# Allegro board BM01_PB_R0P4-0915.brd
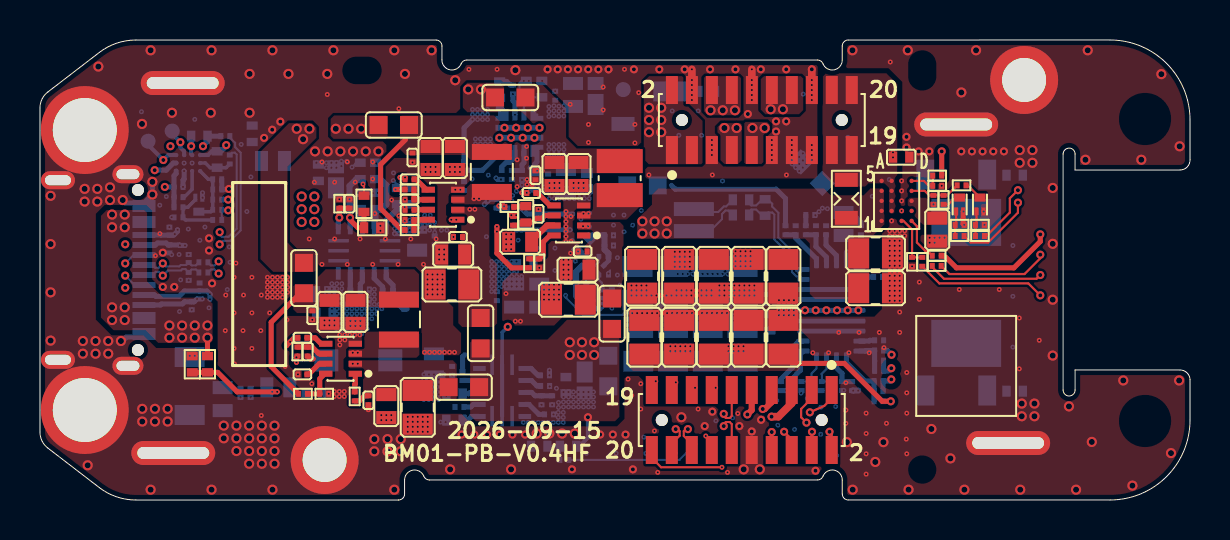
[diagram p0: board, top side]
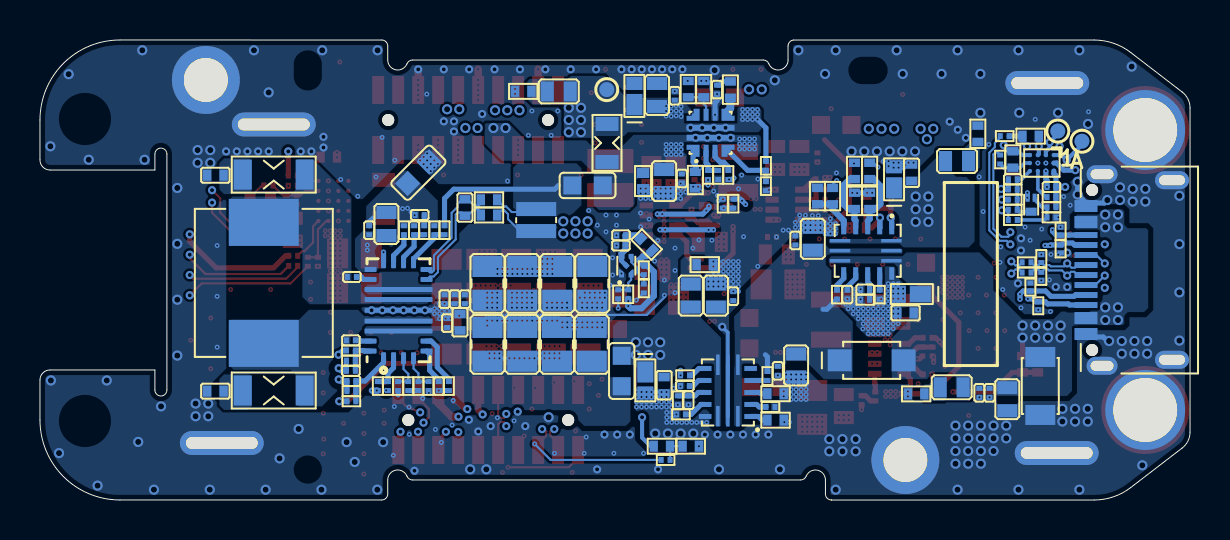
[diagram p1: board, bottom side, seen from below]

Outline 57.54 x 23 mm; copper layers: TOP, GND2, SIG3, SIG4, GND5, BOTTOM. Coordinates in mm from the lower left corner of the outline.
Outline path: 0,19.61 arc(0.1,20.05) 0.39,20.4 2.97,22.38 arc(3.83,22.84) 4.8,23 19.83,23 arc(20.03,22.91) 20.11,22.7 20.11,22 arc(20.52,21.51) 21.08,21.81 arc(21.19,21.95) 21.35,22 38.9,22 arc(39.07,21.95) 39.18,21.81 arc(39.74,21.51) 40.14,22 40.14,22.7 arc(40.23,22.91) 40.44,23 53.54,23 arc(56.37,21.83) 57.54,19 57.54,17.02 arc(57.4,16.65) 57.04,16.5 51.79,16.5 51.79,17.3 arc(51.49,17.6) 51.19,17.3 51.19,5.5 arc(51.49,5.2) 51.79,5.5 51.79,6.5 57.04,6.5 arc(57.39,6.36) 57.54,6.02 57.54,4 arc(56.37,1.17) 53.54,0 40.44,0 arc(40.23,0.09) 40.14,0.3 40.14,1 arc(39.74,1.49) 39.18,1.19 arc(39.07,1.05) 38.9,1 19.48,1 arc(19.32,1.05) 19.21,1.19 arc(18.65,1.49) 18.24,1 18.24,0.3 arc(18.15,0.09) 17.94,0 4.8,0 arc(3.83,0.16) 2.97,0.62 0.39,2.6 arc(0.1,2.95) 0,3.39 0,19.61

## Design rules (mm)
constraint set DEFAULT: min track width 0.107, pair gap 0.127
net group 90_BILLBOARD_D_X1: nets 90_BILLBOARD_DN_X1 90_BILLBOARD_DP_X1
net group 90_BILLBOARD_D_X2: nets 90_BILLBOARD_DN_X2 90_BILLBOARD_DP_X2
net group DP1: nets DSP_SBU1_X3 DSP_SBU2_X3
net group PW_5V_SENSE_: nets PW_5V_SENSE_N PW_5V_SENSE_P
net group 20V: nets MT7231_MOUT PD_USP_VBUS_X1 PW_5V_VIN VCC5-20V_SYS_X1 VCC5-20V_SYS_X2 VCC5-20V_SYS_X3
net group DP2: nets N17338604
nets with their own width: min track width 0.109; nets CHARGE_OC CHARGE_PE1 CHG_VBUS_MON GPIO2_CHG_VBUS_DISCHARGE GPIO4_CHG_VBUS_CTRL GPIO5_PLUG_VBUS_DISCHARGE GPIO6_PLUG_VBUS_CTRL

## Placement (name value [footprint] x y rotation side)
C501  2.2nF/50V  [C0402]  48.77 5.44 0 bottom
C502  2.2nF/50V  [C0402]  48.77 16.24 0 bottom
C503  22uF/25V  [C0805]  35.15 7.78 90 bottom
C504  22uF/25V  [C0805]  33.41 7.78 90 bottom
C505  100nF/25V  [C0201]  41.99 7.99 180 bottom
C506  100nF/25V  [C0201]  41.93 11.15 180 bottom
C507  1uF/25V  [C0402]  36.53 8.89 90 bottom
C508  100nF/25V  [C0201]  37.17 8.85 90 bottom
C509  4.7uF/25V  [C0603]  40.21 13.8 270 bottom
C510  100nF/25V  [C0201]  41.07 13.49 270 bottom
C511  100nF/25V  [C0201]  41.99 6.46 180 bottom
C512  100nF/25V  [C0201]  41.96 5.95 0 bottom
C513  47uF/10V  [C0805]  35.15 10.83 270 bottom
C514  47uF/10V  [C0805]  33.41 10.83 270 bottom
C515  47uF/10V  [C0805]  31.66 10.83 270 bottom
C516  100nF/25V  [C0201]  36.79 10.04 270 bottom
C517  100nF/25V  [C0201]  37.3 10.04 270 bottom
C518  100nF/25V  [C0201]  36.28 10.04 270 bottom
C519  10nF/25V  [C0201]  37.59 5.7 90 bottom
C520  220nF/25V  [C0402]  36.28 14.63 90 bottom
C521  100pF/50V  [C0201]  38.82 13.49 90 bottom
C522  10nF/25V  [C0201]  38.54 14.25 0 bottom
C523  100nF/10V  [C0201]  28.47 12.73 0 bottom
C524  10nF/25V  [C0201]  28.47 13.23 0 bottom
C525  47uF/10V  [C0805]  29.9 10.83 270 bottom
C526  22uF/25V  [C0805]  30.24 8.14 90 top
C527  22uF/25V  [C0805]  31.98 8.14 90 top
C528  22uF/25V  [C0805]  33.72 8.14 90 top
C529  22uF/25V  [C0805]  29.93 7.78 90 bottom
C530  22uF/25V  [C0805]  35.46 8.14 90 top
C531  22uF/25V  [C0805]  31.67 7.78 90 bottom
C532  22uF/25V  [C0805]  37.2 8.14 90 top
C533  47uF/10V  [C0805]  33.72 11.19 270 top
C534  47uF/10V  [C0805]  30.13 11.19 270 top
C535  47uF/10V  [C0805]  31.98 11.19 270 top
C536  47uF/10V  [C0805]  35.46 11.19 270 top
C537  47uF/10V  [C0805]  37.2 11.19 270 top
C601  4.7uF/35V  [C0603]  18.87 13.06 90 bottom
C602  4.7uF/35V  [C0603]  11.92 5.64 0 bottom
C603  100nF/35V  [C0201]  19.75 12.98 90 bottom
C604  4.7uF/35V  [C0603]  11.66 16.95 180 bottom
C605  1uF/35V  [C0402]  14.24 9.36 0 bottom
C606  1uF/35V  [C0402]  13.93 16.37 90 bottom
C607  100nF/25V  [C0201]  16.26 10.52 0 bottom
C608  100nF/25V  [C0201]  15.49 14.82 90 top
C609  10nF/25V  [C0201]  17.14 10.27 270 bottom
C610  4.7uF/35V  [C0603]  19.71 6.73 270 bottom
C611  100nF/35V  [C0201]  20.62 6.46 270 bottom
C612  4.7uF/35V  [C0603]  24.98 10.22 90 bottom
C613  1uF/35V  [C0402]  26.31 5.74 270 bottom
C614  100nF/35V  [C0201]  22.86 10.2 90 bottom
C615  4.7uF/35V  [C0603]  23.72 10.22 90 bottom
C616  100nF/25V  [C0201]  25.09 4.99 270 bottom
C617  10nF/25V  [C0201]  25.28 5.7 0 bottom
C701  22uF/25V  [C0805]  26.44 10.02 180 top
C702  10uF/25V  [C0603]  26.9 11.51 180 top
C703  100nF/25V  [C0201]  27.15 12.43 180 top
C704  100nF/25V  [C0201]  24.59 15.35 180 top
C705  22uF/10V  [C0603]  25.74 16.3 270 top
C706  22uF/10V  [C0603]  26.95 16.3 270 top
C707  100nF/10V  [C0201]  24.79 16.24 270 top
C708  68nF/50V  [C0603]  24.03 12.91 180 top
C709  100nF/25V  [C0201]  24.94 14.31 90 top
C710  22uF/25V  [C0805]  18.9 4.63 270 top
C711  10uF/25V  [C0603]  17.33 4.7 270 top
C712  100nF/25V  [C0201]  16.43 4.99 270 top
C713  100nF/25V  [C0201]  13.13 8.11 180 top
C714  22uF/10V  [C0603]  14.49 9.41 270 top
C715  22uF/10V  [C0603]  15.78 9.41 270 top
C716  100nF/25V  [C0201]  13.39 7.42 270 top
C717  100nF/10V  [C0201]  13.63 9.24 270 top
C718  10nF/25V  [C0201]  13.13 6.28 180 top
C719  22uF/25V  [C0805]  20.61 10.78 180 top
C720  10uF/25V  [C0603]  20.67 12.28 180 top
C721  100nF/25V  [C0201]  20.92 13.15 180 top
C722  100nF/25V  [C0201]  18.49 16.04 180 top
C723  22uF/10V  [C0603]  19.54 17.1 270 top
C724  22uF/10V  [C0603]  20.76 17.1 270 top
C725  100nF/10V  [C0201]  18.64 17.13 270 top
C726  100nF/25V  [C0201]  18.49 15.02 180 top
C727  10nF/25V  [C0201]  18.49 14.51 180 top
C801  100nF/35V  [C0201]  10.03 5.36 270 bottom
C802  4.7uF/35V  [C0603]  9.14 5.04 270 bottom
C803  100nF/35V  [C0201]  10.54 5.36 270 bottom
C804  1uF/10V  [C0201]  6.93 15.65 0 bottom
C805  100nF/10V  [C0201]  8.87 16.04 0 bottom
C901  22uF/10V  [C0603]  26.31 15.95 270 bottom
C902  100nF/25V  [C0201]  25.42 16.08 270 bottom
C903  100nF/25V  [C0201]  25.78 20.22 90 bottom
C904  4.7uF/35V  [C0603]  31.58 20.43 0 bottom
C905  22uF/10V  [C0603]  26.67 20.25 90 bottom
C907  3.3nF/25V  [C0201]  23.67 20.52 270 bottom
C1101  22uF/25V  [C0805]  41.81 12.33 0 top
C1102  22uF/25V  [C0805]  41.81 10.59 0 top
C1103  4.7uF/35V  [C0603]  44.89 13.52 270 top
C1104  1uF/25V  [C0402]  43.09 17.14 0 top
D601  LMBR4020H3T5G  [DFN_2P_1D05_1D6X0D8_H0D42-CA]  13.92 10.3 0 bottom
D602  LMBR4020H3T5G  [DFN_2P_1D05_1D6X0D8_H0D42-CA]  14.81 16.04 90 bottom
D603  LMBR4020H3T5G  [DFN_2P_1D05_1D6X0D8_H0D42-CA]  27.25 5.98 270 bottom
D606  LMBR340FT1G  [SOD123_2P_3D2_3D65X1D75_H1D15_CA]  15.93 6.98 180 bottom
D901  LMBR4020H3T5G  [DFN_2P_1D05_1D6X0D8_H0D42-CA]  27.8 20.2 90 bottom
H1  Mechanical HOLE  [PAD-C4D4D3D2]  2.24 18.5 0 top
H2  Mechanical HOLE  [PAD-C4D4D3D2]  2.24 4.5 0 top
H3  Mechanical HOLE  [PAD-C4D2D2]  14.24 2 0 top
H4  Mechanical HOLE  [PAD-C4D2D2]  49.24 21 0 top
H5  Mechanical HOLE  [PAD-O4D6X1D6D3D6X0D6]  7.14 20.85 0 top
H6  Mechanical HOLE  [PAD-O4D6X1D6D3D6X0D6]  6.67 2.35 0 top
H7  Mechanical HOLE  [PAD-O4D6X1D6D3D6X0D6]  45.84 18.78 0 top
H8  Mechanical HOLE  [PAD-O4D6X1D6D3D6X0D6]  48.44 2.85 0 top
J801  UCA11-1600B2ANL-H03  [TYPEC_16-4P_0D5_10D24X7D35_H4D7]  3.23 11.5 90 bottom
J1001  1mm_pitch_10x2 Male Connector  [FH_2X10P_1_10D2X3D8_H2D55]  36.12 19 0 top
J1002  1mm_pitch_10x2 Male Connector  [FH_2X10P_1_10D2X3D8_H2D55]  35.11 4 180 top
L501  4.7uH/8A  [L_2P_6D05_7D3X6D8_H3]  46.34 10.86 90 bottom
L701  4.7uH/1.3A  [L_2P_1D7_2D5X2_H1D2]  29.01 16.1 90 top
L702  1.5uH/2.5A  [L_2P_2_2D5X2_H1D2]  17.96 9.02 90 top
L703  1.5uH/2.5A  [L_2P_2_2D5X2_H1D2]  22.61 16.4 90 top
Q801  L2N7002KN3T5G  [SOT883_3P_0D35_0D6X1_H0D53]  7.95 14.77 0 bottom
Q1101  L2N7002KN3T5G  [SOT883_3P_0D35_0D6X1_H0D53]  46.02 14.78 0 top
Q1102  L2N7002KN3T5G  [SOT883_3P_0D35_0D6X1_H0D53]  47.03 14.78 0 top
R501  2.2R_1%  [R1206]  45.85 5.48 180 bottom
R502  2.2R_1%  [R1206]  45.85 16.27 180 bottom
R503  0R  [R0201]  40.64 5.7 270 bottom
R504  0R  [R0201]  41.99 7.48 0 bottom
R506  0R  [R0201]  40.13 5.7 90 bottom
R507  0R  [R0201]  41.99 6.97 180 bottom
R508  147K_1%  [R0201]  41.96 4.94 180 bottom
R509  115K_1%  [R0201]  41.96 5.44 180 bottom
R510  10mOHM  [R0508_1P25X2]  32.72 14 90 bottom
R511  100K_1%  [R0201]  37.3 13.49 90 bottom
R512  10R_1%  [R0402]  35.08 14.25 180 bottom
R513  10R_1%  [R0402]  35.08 15.01 180 bottom
R514  49.9K_1%  [R0201]  37.08 5.7 270 bottom
R515  30.1K_1%  [R0201]  37.81 13.49 270 bottom
R516  150K_1%  [R0201]  39.33 13.49 270 bottom
R517  10K_1%  [R0201]  38.32 13.49 270 bottom
R518  0R_1%  [R0402]  27.19 12.77 45 bottom
R520  0R  [R0201]  39.62 5.7 270 bottom
R521  0R  [R0201]  38.1 5.7 270 bottom
R522  0R  [R0201]  27.33 10.58 90 bottom
R523  0R  [R0201]  28.61 10.28 90 bottom
R524  10K  [R0201]  39.12 5.7 90 bottom
R525  10K  [R0201]  38.61 5.7 90 bottom
R526  10K  [R0201]  27.33 11.49 270 bottom
R527  10K  [R0201]  28.11 10.28 90 bottom
R601  3.6R_1%  [R0402]  10.62 18.31 270 bottom
R602  3.6R_1%  [R0402]  13.7 5.31 180 bottom
R603  0R_1%  [R0402]  16.03 16.45 90 bottom
R604  0R_1%  [R0402]  17.88 15.2 90 bottom
R605  0R_1%  [R0402]  16.21 14.81 270 top
R606  0R_1%  [R0402]  16.79 16.45 270 bottom
R607  10K  [R0201]  17.66 10.27 90 bottom
R608  100K_1%  [R0402]  18.64 15.2 270 bottom
R609  100K_1%  [R0402]  16.03 14.96 270 bottom
R610  100K_1%  [R0402]  16.62 13.61 180 top
R611  100K_1%  [R0402]  16.79 14.96 270 bottom
R612  8.2K_1%  [R0201]  16.26 10.02 180 bottom
R613  8.2K_1%  [R0201]  14.98 14.82 270 top
R614  200K_1%  [R0201]  15.53 10.27 90 bottom
R615  10K  [R0201]  21.14 6.2 90 bottom
R616  4.7K  [R0402]  20.74 5.31 0 bottom
R617  4.7K  [R0402]  20.74 3.99 0 bottom
R618  3.6R_1%  [R0402]  24.28 11.77 0 bottom
R619  10K  [R0201]  25.27 6.23 180 bottom
R620  10K  [R0201]  20.99 4.65 0 bottom
R621  8.2K_1%  [R0201]  25.63 4.99 90 bottom
R622  200K_1%  [R0201]  25.47 4.28 180 bottom
R623  330K_1%  [R0402]  26.42 2.69 0 bottom
R624  47K_1%  [R0402]  24.98 2.69 0 bottom
R625  0R  [R0201]  26.24 2 180 bottom
R701  300K_1%  [R0201]  23.67 13.97 270 top
R703  3.16K_1%  [R0201]  24.48 11.83 270 top
R704  0R  [R0201]  23.48 14.66 180 top
R705  1K_1%  [R0201]  24.99 11.83 90 top
R706  300K_1%  [R0201]  12.88 7.42 90 top
R707  10K_1%  [R0201]  13.16 5.31 180 top
R708  20K_1%  [R0201]  14.23 5.31 180 top
R709  100K  [R0201]  15.75 5.18 90 top
R710  300K_1%  [R0201]  18.49 15.53 0 top
R711  2.49K_1%  [R0201]  18.49 13.5 180 top
R712  20K_1%  [R0201]  18.49 14 0 top
R713  42.2K_1%  [R0201]  23.38 14.82 270 bottom
R714  100K_1%  [R0201]  22.85 14.82 270 bottom
R715  22K_1%  [R0402]  24.31 14.28 270 top
R801  100K  [R0201]  6.93 15.15 180 bottom
R802  10K  [R0201]  8.87 15.02 180 bottom
R803  10K  [R0201]  6.93 14.64 0 bottom
R804  10K  [R0201]  8.87 15.53 0 bottom
R805  0R  [R0201]  8.87 14 0 bottom
R806  10K  [R0201]  6.93 14.13 180 bottom
R807  0R_1%  [R0402]  7.97 18.19 0 bottom
R808  0R_1%  [R0402]  8.86 17.03 270 bottom
R809  0R  [R0201]  8.87 14.51 0 bottom
R810  0R  [R0201]  8.18 11.88 180 bottom
R811  0R  [R0201]  8.18 11.37 180 bottom
R812  0R  [R0201]  9.27 18.19 180 bottom
R813  0R  [R0201]  9.5 17.03 270 bottom
R901  0R  [R0805]  29.17 17.85 90 bottom
R902  100K  [R0402]  24.75 16 90 bottom
R903  0R  [R0402]  23 20.52 270 bottom
R904  47K_1%  [R0201]  24.12 16.25 270 bottom
R905  33K_1%  [R0201]  21.22 16.71 90 bottom
R906  3.6R_1%  [R0402]  33.36 20.43 180 bottom
R907  1.1K_1%  [R0402]  24.33 20.55 270 bottom
R908  10K_1%  [R0201]  23.1 16.25 90 bottom
R909  12K_1%  [R0201]  21.22 15.69 90 bottom
R910  10K_1%  [R0201]  23.61 16.25 90 bottom
R911  0R  [R0402]  25.11 20.55 90 bottom
R1001  330K_1%  [R0402]  8.38 6.79 90 top
R1002  47K_1%  [R0402]  7.62 6.79 270 top
R1101  0R  [R0805]  40.35 15.06 90 top
R1102  30K_1%  [R0201]  44.7 15.01 90 top
R1103  84.5K_1%  [R0201]  45.21 15.01 90 top
R1104  30K_1%  [R0201]  46.11 15.73 180 top
R1105  0R  [R0201]  46.02 13.2 0 top
R1106  0R  [R0201]  47.03 13.2 0 top
R1107  10K_1%  [R0201]  46.02 13.76 180 top
R1108  10K_1%  [R0201]  47.03 13.76 180 top
R1109  0R  [R0201]  44.87 11.71 180 top
R1110  0R  [R0201]  44.14 11.91 90 top
R1111  10K_1%  [R0201]  43.64 11.91 90 top
R1112  10K_1%  [R0201]  44.87 12.22 180 top
R1113  160K_1%  [R0201]  44.89 16.22 0 top
R1114  10K_1%  [R0201]  44.89 15.71 180 top
SL501  -  [SL0603]  28.43 6.45 270 bottom
SL502  -  [SL0603]  30.14 15.73 180 bottom
SL503  -  [SL0603]  38.61 16.37 135 bottom
SL701  -  [SL0603]  23.53 20.12 180 top
SL702  -  [SL0603]  28.63 9.32 90 top
SL703  -  [SL0603]  21.21 5.64 180 top
SL704  -  [SL0603]  13.21 11.1 90 top
SL705  -  [SL0603]  22.05 8.34 90 top
SL706  -  [SL0603]  17.7 18.75 180 top
TP801  X_Testpoint_SMDC20  [TPC30]  5.41 17.94 0 bottom
TP802  X_Testpoint_SMDC20  [TPC30]  6.62 18.45 0 bottom
TP901  TP  [TPC30]  29.18 20.52 180 bottom
TVS801  SMF20CA  [SOD123_2P_2D9_3D75X1D75_H1D2]  7.49 5.7 90 bottom
TVS802  AR0521P0LV  [DFN_2P_0D4_0D6X0D3_H0D34]  6.48 13.44 270 bottom
TVS803  AR0521P0LV  [DFN_2P_0D4_0D6X0D3_H0D34]  6.48 12.56 90 bottom
TVS804  AR0521P0LV  [DFN_2P_0D4_0D6X0D3_H0D34]  7.59 9.71 90 bottom
TVS805  AR0521P0LV  [DFN_2P_0D4_0D6X0D3_H0D34]  7.44 11.18 90 bottom
TVS806  AR0521P0LV  [DFN_2P_0D4_0D6X0D3_H0D34]  7.44 12.07 270 bottom
TVS807  AR0521P0LV  [DFN_2P_0D4_0D6X0D3_H0D34]  7.99 10.65 270 bottom
TVS901  JEB07DF  [DFN_2P_0D8_1X0D6_H0D55]  27.37 15.95 270 bottom
U501  TPS55289RYQR  [VQFN_21P_0D5_5X3_H1]  39.6 9.49 90 bottom
U502  TMP110DIDPWR  [X2SON_5P_0D48_0D8X0D8_H0D4]  28.21 11.72 180 bottom
U601  MT7232NQJR  [QFN_16P_0D5_2D5X3D2_H0D8]  16.13 12.46 270 bottom
U602  MT7231NQJR  [QFN_16P_0D5_2D5X3D2_H0D8]  23.12 5.38 0 bottom
U701  LA3522BS  [SOT583_8P_0D5_2D1X1D6_H0D6]  26.47 13.98 90 top
U702  LA3522BS  [SOT583_8P_0D5_2D1X1D6_H0D6]  15.04 7.06 90 top
U703  LA3522BS  [SOT583_8P_0D5_2D1X1D6_H0D6]  20.17 14.77 90 top
U801  NX20P0407UKAZ  [WLCSP_12P_0D4_1D27X1D67_H0D57]  7.41 16.85 270 bottom
U901  LM73100RPWR  [VQFN-HR-10P_0D475_2X2_H1]  23.99 18.36 90 bottom
U1101  KTS1865CEIAA-TA  [WLCSP_20P_0D5_2D71X2D16_H0D6]  42.86 14.96 90 top

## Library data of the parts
C501-C537 C601-C617 C701-C727 C801-C805 C901-C905 C907 C1101-C1104 = Cap_np
D601-D603 D606 D901 = SBD-A
H1-H8 = Mechanical HOLE
J801 = UCB11-1600B1ANL-H06
J1001 J1002 = HEADER 20X2_5
L501 L701-L703 = Coil
Q801 Q1101 Q1102 = NMOS-L2N7002KN3T5G
R501-R504 R506-R509 R511-R518 R520-R527 R601-R625 R701 R703-R715 R801-R813 R901-R911 R1001 R1002 R1101-R1114 = Resistor
R510 = TRL050810FR010P05Z
SL501-SL503 SL701-SL706 = SL0603
TP801 TP802 = J PCB_TP_SMDC20
TP901 = TP
TVS801-TVS807 TVS901 = TVS-BiA
U501 = BUCK&BOOST-PTPS55289RYQR
U502 = TMP110DIDPWR
U601 = Power Switch-MT7232NQJR
U602 = Power Switch-MT7231NQJR
U701-U703 = LA3522BS
U801 = NX20P0407UKAZ
U901 = LM73100RPWR
U1101 = KTS1865CEIAA-TA

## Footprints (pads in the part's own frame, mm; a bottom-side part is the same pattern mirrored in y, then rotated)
C0201
  rect 0.25x0.3 smd: 1(-0.225,0) 2(0.225,0)
C0402
  rect 0.42x0.55 smd: 1(-0.41,0) 2(0.41,0)
C0603
  rect 0.65x1 smd: 1(-0.575,0) 2(0.575,0)
C0805
  rect 1.05x1.5 smd: 1(-0.845,0) 2(0.845,0)
DFN_2P_0D4_0D6X0D3_H0D34
  rect 0.25x0.3 smd: 1(-0.2,0) 2(0.2,0)
DFN_2P_0D8_1X0D6_H0D55
  rect 0.5x0.6 smd: 1(-0.4,0) 2(0.4,0)
DFN_2P_1D05_1D6X0D8_H0D42-CA
  rect 1.05x0.8 smd: 1(-0.425,0)
  rect 0.65x0.8 smd: 2(0.625,0)
FH_2X10P_1_10D2X3D8_H2D55
  round 0.6 hole 0.6 unplated: (-4,0) (4,0)
  rect 0.6x1.4 smd: 1(-4.5,-1.5) 2(-4.5,1.5) 3(-3.5,-1.5) 4(-3.5,1.5) 5(-2.5,-1.5) 6(-2.5,1.5) 7(-1.5,-1.5) 8(-1.5,1.5) 9(-0.5,-1.5) 10(-0.5,1.5) 11(0.5,-1.5) 12(0.5,1.5) 13(1.5,-1.5) 14(1.5,1.5) 15(2.5,-1.5) 16(2.5,1.5) 17(3.5,-1.5) 18(3.5,1.5) 19(4.5,-1.5) 20(4.5,1.5)
L_2P_1D7_2D5X2_H1D2
  rect 1.2x2.3 smd: 1(-0.85,0) 2(0.85,0)
L_2P_2_2D5X2_H1D2
  rect 0.8x2 smd: 1(-1,0) 2(1,0)
L_2P_6D05_7D3X6D8_H3
  rect 2.35x3.5 smd: 1(-3.025,0) 2(3.025,0)
PAD-C4D2D2
  round 3.4 hole 2.2: 1(0,0)
PAD-C4D4D3D2
  round 4.4 hole 3.2: 1(0,0)
PAD-O4D6X1D6D3D6X0D6
  oval 4.2x1.2 hole 3.6x0.6: 1(0,0)
QFN_16P_0D5_2D5X3D2_H0D8
  rect 0.627x0.25 smd: 1(-1.136,1.2) 2(-1.136,0.6) 3(-1.136,0) 4(-1.136,-0.6) 5(-1.136,-1.2) 9(1.136,-1.2) 10(1.136,-0.6) 11(1.136,0) 12(1.136,0.6) 13(1.136,1.2)
  rect 0.175x1.027 smd: 6(-0.5,-1.387) 7(0,-1.387) 8(0.5,-1.387) 14(0.5,1.186) 15(0,1.186) 16(-0.5,1.186)
R0201
  rect 0.25x0.3 smd: 1(-0.225,0) 2(0.225,0)
R0402
  rect 0.42x0.55 smd: 1(-0.41,0) 2(0.41,0)
R0508_1P25X2
  rect 0.7x2 smd: 1(-0.55,0) 2(0.55,0)
R0805
  rect 0.7x1.15 smd: 1(-0.95,0) 2(0.95,0)
R1206
  rect 0.9x1.5 smd: 1(-1.55,0) 2(1.55,0)
SL0603
  rect 0.9x0.9 smd: 1(-0.762,0) 2(0.762,0)
SOD123_2P_2D9_3D75X1D75_H1D2
  rect 1x1.5 smd: 1(-1.45,0) 2(1.45,0)
SOD123_2P_3D2_3D65X1D75_H1D15_CA
  rect 1.2x1.1 smd: 1(-1.6,0) 2(1.6,0)
SOT583_8P_0D5_2D1X1D6_H0D6
  rect 0.3x0.67 smd: 1(-0.75,-0.74) 2(-0.25,-0.74) 3(0.25,-0.74) 4(0.75,-0.74) 5(0.75,0.74) 6(0.25,0.74) 7(-0.25,0.74) 8(-0.75,0.74)
SOT883_3P_0D35_0D6X1_H0D53
  rect 0.2x0.4 smd: 1(-0.175,-0.35) 2(0.175,-0.35)
  rect 0.55x0.4 smd: 3(0,0.35)
TPC30
  round 0.75 smd: 1(0,0)
TYPEC_16-4P_0D5_10D24X7D35_H4D7
  round 0.6 hole 0.6 unplated: (-4,1.668) (4,1.668)
  rect 0.3x1.15 smd: A1(-3.35,1.973) A4(-2.55,1.973) A5(-1.25,1.973) A6(-0.25,1.973) A7(0.25,1.973) A8(1.25,1.973) A9(2.55,1.973) A12(3.35,1.973) B1(3.05,1.973) B4(2.25,1.973) B5(1.75,1.973) B6(0.75,1.973) B7(-0.75,1.973) B8(-1.75,1.973) B9(-2.25,1.973) B12(-3.05,1.973)
  oval 0.9x1.55 hole 0.5x1.15: G1(-4.79,1.167) G2(4.79,1.167)
  oval 0.9x1.7 hole 0.5x1.3: G3(-4.49,-2.332) G4(4.49,-2.332)
VQFN-HR-10P_0D475_2X2_H1
  custom 0.15x0.15 smd: 1(-0.9,0.875) 4(-0.9,-0.875) 7(0.9,-0.875) 10(0.9,0.875)
  rect 0.6x0.25 smd: 2(-0.9,0.225) 3(-0.9,-0.225) 8(0.9,-0.225) 9(0.9,0.225)
  rect 0.3x2.4 smd: 5(-0.25,0) 6(0.25,0)
VQFN_21P_0D5_5X3_H1
  rrect 0.6x0.25 smd: 1(-2.4,0.75) 2(-2.4,0.25) 3(-2.4,-0.25) 4(-2.4,-0.75) 14(2.4,-0.75) 15(2.4,-0.25) 16(2.4,0.25) 17(2.4,0.75)
  rrect 0.25x0.6 smd: 5(-2.04,-1.4) 6(-1.54,-1.4) 12(1.54,-1.4) 13(2.04,-1.4) 18(2.04,1.4) 19(1.54,1.4) 20(-1.54,1.4) 21(-2.04,1.4)
  rrect 0.25x3.4 smd: 7(-1.04,0) 8(-0.54,0) 9(0,0) 10(0.54,0) 11(1.04,0)
WLCSP_12P_0D4_1D27X1D67_H0D57
  round 0.22 smd: A1(-0.4,0.6) A2(0,0.6) A3(0.4,0.6) B1(-0.4,0.2) B2(0,0.2) B3(0.4,0.2) C1(-0.4,-0.2) C2(0,-0.2) C3(0.4,-0.2) D1(-0.4,-0.6) D2(0,-0.6) D3(0.4,-0.6)
WLCSP_20P_0D5_2D71X2D16_H0D6
  round 0.22 smd: A1(-1,0.75) A2(-0.5,0.75) A3(0,0.75) A4(0.5,0.75) A5(1,0.75) B1(-1,0.25) B2(-0.5,0.25) B3(0,0.25) B4(0.5,0.25) B5(1,0.25) C1(-1,-0.25) C2(-0.5,-0.25) C3(0,-0.25) C4(0.5,-0.25) C5(1,-0.25) D1(-1,-0.75) D2(-0.5,-0.75) D3(0,-0.75) D4(0.5,-0.75) D5(1,-0.75)
X2SON_5P_0D48_0D8X0D8_H0D4
  custom 0.062x0.062 smd: 1(-0.24,-0.39) 2(0.24,-0.39) 4(0.24,0.39) 5(-0.24,0.39)
  rect 0.25x0.25 smd rot 135: 3(0,0)

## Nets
0V9_BST: C722.1 U703.5
0V9_EN: C726.1 R710.2 U703.6
0V9_FB: R711.1 R712.2 U703.8
0V9_PG: R704.2 R713.2 R714.2 U703.1
0V9_SS: C727.1 U703.7
3V3_BST: C704.1 U701.5
3V3_EN_X1: C709.1 R701.2 R715.2 U701.6
3V3_FB: R703.1 R705.2 U701.8
3V3_SS: C708.1 U701.7
GND: C501.2 C502.2 C503.2 C504.2 C507.2 C508.2 C513.2 C514.2 C515.2 C516.2 C517.2 C518.2 C523.2 C524.2 C525.2 C526.2 C527.2 C528.2 C529.2 C530.2 C531.2 C532.2 C533.2 C534.2 C535.2 C536.2 C537.2 C601.2 C603.2 C605.2 C606.2 C607.2 C608.2 C609.2 C610.2 C611.2 C613.2 C614.2 C615.2 C616.2 C617.2 C701.2 C702.2 C703.2 C705.2 C706.2 C707.2 C708.2 C709.2 C710.2 C711.2 C712.2 C714.2 C715.2 C716.2 C717.2 C718.2 C719.2 C720.2 C721.2 C723.2 C724.2 C725.2 C726.2 C727.2 C801.2 C802.2 C803.2 C804.2 C805.2 C901.2 C902.2 C903.2 C905.2 C907.2 C1101.2 C1102.2 C1103.2 C1104.2 D601.2 D602.2 D603.2 D901.2 H1.1(HOLE) H2.1(HOLE) H3.1(HOLE) H4.1(HOLE) H5.1(HOLE) H6.1(HOLE) H7.1(HOLE) H8.1(HOLE) J801.A1 J801.A12 J801.B1 J801.B12 J801.G1 J801.G2 J801.G3 J801.G4 J1001.4 J1001.5 J1001.10 J1001.11 J1001.13 J1001.15 J1001.16 J1002.10 Q801.2(SOURCE) Q1101.2(SOURCE) Q1102.2(SOURCE) R601.1 R602.1 R608.1 R609.1 R610.1 R611.1 R612.1 R613.1 R614.1 R616.1 R617.1 R618.1 R620.1 R621.1 R622.1 R624.1 R705.1 R708.1 R712.1 R713.1 R804.2 R806.2 R902.1 R906.1 R907.1 R909.1 R910.1 R1002.1 R1102.1 R1107.1 R1108.1 R1111.1 R1114.1 SL503.2 TVS801.1 TVS802.1 TVS803.1 TVS804.1 TVS805.1 TVS806.1 TVS807.1 TVS901.2 U501.9 U502.1 U601.13 U602.13 U701.4 U702.4 U703.4 U801.B3 U901.8 U1101.B1 U1101.C3 U1101.C4 U1101.C5
VCC5-20V_SYS: C612.1 C613.1 D603.1(C) R623.2 SL501.1 SL702.1 SL703.1 SL705.1 U602.8 U602.14(VOUT2)
VCC5-20V_SYS_X1: C701.1 C702.1 C703.1 R701.1 SL702.2 U701.2(VIN)
VCC5-20V_SYS_X2: C710.1 C711.1 C712.1 R706.1 R709.1 SL703.2 U702.2(VIN)
VCC5-20V_SYS_X3: C719.1 C720.1 C721.1 R710.1 R714.1 SL705.2 U703.2(VIN)
VCC_0V9: J1001.9 SL706.2
VCC_0V9_X1: C723.1 C724.1 C725.1 L703.2 R711.2 SL706.1
VCC_0V9_X2: C722.2 L703.1 U703.3
VCC_3V3_SYS1: C804.1 J1001.12 J1001.14 R518.1 R524.1 R525.1 R526.1 R527.1 R801.2 R802.1 R803.1 R908.1 R1112.1 SL701.2 U801.A3(VSYS)
VCC_3V3_SYS1_X1: C705.1 C706.1 C707.1 L701.2 R703.2 SL701.1
VCC_3V3_SYS1_X2: C704.2 L701.1 U701.3
VDD12: J1001.6 J1001.8 SL704.2
VDD12_BST: C713.1 U702.5
VDD12_EN: C716.1 R706.2 U702.6
VDD12_FB: R707.1 R708.2 U702.8
VDD12_PG: R709.2 U702.1
VDD12_SS: C718.1 U702.7
VDD12_X1: C714.1 C715.1 C717.1 L702.2 R707.2 SL704.1
VDD12_X2: C713.2 L702.1 U702.3
90_BILLBOARD_DN_X1: J801.A7 J801.B7 R810.2 TVS806.2
90_BILLBOARD_DN_X2: J1002.11 R810.1
90_BILLBOARD_DP_X1: J801.A6 J801.B6 R811.2 TVS805.2
90_BILLBOARD_DP_X2: J1002.12 R811.1
C_PD_ADA_VBUS1: C602.1 C605.1 C801.1 C802.1 C803.1 D601.1(C) D606.2 J801.A4 J801.A9 J801.B4 J801.B9(VBUS_B9) R1001.2 TVS801.2 U601.8 U601.14
CHARGE_OC: J1002.17 R911.2
CHARGE_PE1: J1002.19 R902.2 U901.1
CHG_CC1: J1002.9 U801.A2
CHG_CC2: J1002.7 U801.B2
CHG_VBUS_MON: J1002.5 R1001.1 R1002.2
DSP_AUX_CTR: C805.1 Q801.3 R802.2 R804.1 R809.1 U801.D3
DSP_CC1_X1: J801.A5 TP801.1(TP) TVS807.2 U801.A1
DSP_CC2_X1: J801.B5 TP802.1(TP) TVS802.2 U801.B1
DSP_SBU1_X1: J801.B8 R807.1 TVS804.2 U801.C1
DSP_SBU1_X2: R807.2 R812.2 U801.C2
DSP_SBU1_X3: J1002.16 R812.1
DSP_SBU2_X1: J801.A8 R808.1 TVS803.2 U801.D1
DSP_SBU2_X2: R808.2 R813.2 U801.D2
DSP_SBU2_X3: J1002.18 R813.1
EN2: R1110.2 R1111.2 U1101.C1
GPIO1_ILIMT_2A: J1002.13 R1105.2
GPIO2_CHG_VBUS_DISCHARGE: J1002.3 R603.2
GPIO4_CHG_VBUS_CTRL: J1002.4 R604.2 R805.2 R809.2
GPIO4_CTRL_X1: Q801.1 R803.2 R805.1 R806.1
GPIO5_PLUG_VBUS_DISCHARGE: J1002.1 R605.1 R1109.1
GPIO6_PLUG_VBUS_CTRL: J1002.2 R606.1
GPIO7_KS1865C_EN: J1002.20 R1110.1
GPIO8_ILIMT_3A: J1002.15 R1106.2
HV_AGND1: C509.1 C510.1 C511.1 C512.2 C519.1 C521.2 C522.2 R506.1 R507.1 R509.1 R514.2 R515.1 R516.1 SL503.1 U501.17
I2C0_SCL_X1: J1002.8 R520.2 R523.1
I2C0_SDA_X1: J1002.6 R521.2 R522.1
MOUT: C601.1 C603.1 C610.1 C611.1 D606.1(C) R607.1 R615.2 U601.7 U601.15 U602.6 U602.16
MOUT_ADC: J1002.14 R625.1
MT7231_DISCI: R620.2 U602.2
MT7231_DISCO: R616.2 U602.3
MT7231_EN: R615.1 U602.4
MT7231_FLTB: R619.2 U602.9
MT7231_ILIM: C616.1 R621.2 U602.11
MT7231_MOUT: C614.1 C615.1 R619.1 U602.7 U602.15
MT7231_NOSS: R617.2 U602.1
MT7231_VLIM: R622.2 U602.12
MT7232_DISC1: R605.2 R610.2 U601.2
MT7232_DISC2: R603.1 R609.2 U601.3
MT7232_EN1: R606.2 R611.2 U601.4
MT7232_EN2: R604.1 R608.2 U601.5
MT7232_FLTB: R607.2 U601.9
MT7232_ILIM1: C607.1 R612.2 U601.11
MT7232_ILIM2: C608.1 R613.2 U601.1
MT7232_VLIM: R614.2 U601.12(VLIM)
OVLO: R904.1 R910.2 U901.2
OVLO_17839094: R1113.1 R1114.2 U1101.D5
PD_USP_VBUS: C1104.1 J1001.17 J1001.18 J1001.19 J1001.20 R1101.2 R1113.2 U1101.A5 U1101.B2 U1101.B3 U1101.B4 U1101.B5
PD_USP_VBUS_X1: C604.1 C606.1 C1101.1 C1102.1 D602.1(C) R1101.1 U601.6 U601.16 U1101.A1 U1101.A2 U1101.A3 U1101.A4(VSYS4)
PP5V0: C903.1 C904.1 C905.1 D901.1(C) J1001.1 J1001.2 J1001.3 R901.2 R905.2 TP901.1 U901.6
PP5V0_SYS: C901.1 C902.1 J1001.7 R901.1 R904.2 SL502.2 TVS901.1 U901.5(VIN)
PW_5V_BOOT1: C505.2 U501.20
PW_5V_BOOT2: C506.2 U501.19
PW_5V_BST_SW1: C505.1 L501.1 R501.2 U501.8
PW_5V_BST_SW2: C506.1 L501.2 R502.2 U501.10
PW_5V_CDC: R516.2 U501.16
PW_5V_COMP: C521.1 R517.2 U501.15
PW_5V_DITH: C519.2 U501.5
PW_5V_EN: C512.1 R508.2 R509.2 U501.1
PW_5V_EXTVCC: C511.2 R504.1 R507.2 U501.21
PW_5V_FB: R511.1 R515.2 U501.14
PW_5V_FSW: R514.1 U501.6
PW_5V_MODE: R503.1 R506.2 U501.2
PW_5V_OUT: C513.1 C514.1 C515.1 C516.1 C517.1 C518.1 C525.1 C533.1 C534.1 C535.1 C536.1 C537.1 R510.1 R512.2 U501.11(VOUT)
PW_5V_SENSE_N: C520.2 R513.1 U501.13
PW_5V_SENSE_P: C520.1 R512.1 U501.12
PW_5V_VCC: C509.2 C510.2 R503.2 R504.2 U501.18
PW_5V_VIN: C503.1 C504.1 C507.1 C508.1 C526.1 C527.1 C528.1 C529.1 C530.1 C531.1 C532.1 R508.1 SL501.2 U501.7
SBU_PROT_FLT: R801.1 U801.C3
STS2_ADD: C523.1 C524.1 R518.2 U502.3 U502.5(V+)
TPS55289_I2C0_SCL_X1: R520.1 R524.2 U501.3
TPS55289_I2C0_SDA_X1: R521.1 R525.2 U501.4
TS2_SCL_X1: R523.2 R527.2 U502.2
TS2_SDA_X1: R522.2 R526.2 U502.4
N17338285: C502.1 R502.1
N17338604: R510.2(R) R511.2 R513.2 SL502.1
N17338820: C522.1 R517.1
N17369623: C617.1 U602.10
N17399398: C612.2 R618.2
N17402193: C609.1 U601.10
N17404682: C604.2 R601.2
N17484520: C602.2 R602.2
N17646610: R704.1 R715.1
N17796413: C904.2 R906.2
N17828259: R905.1 R909.2 U901.4
N17829516: R908.2 U901.3
N17829521: R907.2 R911.1 U901.9
N17829622: R903.2 U901.7
N17839181: R1102.2 R1103.2 R1104.2 U1101.D4
N17839235: C1103.1 U1101.D3
N17839251: Q1102.3 R1104.1
N17839328: Q1101.1 R1105.1 R1107.2
N17839336: Q1102.1 R1106.1 R1108.2
N17850318: R1109.2 U1101.C2
N17850490: Q1101.3 R1103.1
N17851575: R623.1 R624.2 R625.2
N17873017: R1112.2 U1101.D1
N17894716: C501.1 R501.1
N178293080: C907.1 R903.1

Pads without a net: U602 5; U701 1; U901 10; U1101 D2

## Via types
v1: diameter 0.25, hole 0.1, TOP to GND2, 592 vias
v2: diameter 0.406, hole 0.203, GND2 to GND5, 451 vias
v3: diameter 0.25, hole 0.1, GND5 to BOTTOM, 687 vias
v4: diameter 0.406, hole 0.203, TOP to BOTTOM, 117 vias
v5: diameter 0.508, hole 0.305, TOP to BOTTOM, 180 vias

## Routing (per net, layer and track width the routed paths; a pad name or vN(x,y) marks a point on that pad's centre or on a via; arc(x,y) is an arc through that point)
0V9_BST: length 0.9
  TOP w0.254: C722.1 18.82,16.04 19.34,15.52 U703.5
0V9_EN: length 1.2
  TOP w0.254: U703.6 19,15.02 19,15.02 C726.1 R710.2
0V9_FB: length 1.2
  TOP w0.254: U703.8 19.04,14.02 19.02,14 R712.2 R711.1
0V9_PG: length 5
  TOP w0.254: R704.2 23.24,14.66 v1(23.22,14.68) 23.19,14.71 v1(22.96,14.71) ; v1(20.83,14.02) v1(20.58,14.02)
  GND2 w0.254: v2(21.16,13.94) 21.08,14.02 v1(20.83,14.02) v1(20.58,14.02) ; v1(23.22,14.68) 23.19,14.71 v1(22.96,14.71) 22.7,14.44 v2(22.7,14.42)
  SIG4 w0.305: v2(22.7,14.42) 22.7,14.2 22.35,13.85 21.24,13.85 v2(21.16,13.94)
  GND5 w0.254: v3(23.33,14.59) v3(23.08,14.59) 22.87,14.59 v2(22.7,14.42)
  BOTTOM w0.254: R714.2 v3(23.08,14.59) v3(23.33,14.59) R713.2
0V9_SS: length 0.7
  TOP w0.254: C727.1 18.97,14.51 18.98,14.52 U703.7
3V3_BST: length 1.2
  TOP w0.254: U701.5 25.52,14.73 24.89,15.35 C704.1
3V3_EN_X1: length 2.3
  TOP w0.254: U701.6 25.27,14.23 25.12,14.08 C709.1 24.84,14.08 24.63,13.87 R715.2 24.05,13.87 23.91,13.74 R701.2
3V3_FB: length 2.1
  TOP w0.254: U701.8 25.51,13.23 25.18,12.9 25.18,12.26 R705.2 R703.1
3V3_SS: length 1.5
  TOP w0.305: C708.1 24.6,12.96 25.37,13.73 U701.7
GND: length 22.4
  TOP w0.254: C712.2 v1(16.43,4.52) ; v1(13.66,7.06) 13.53,7.06 C716.2 ; Q1101.2 46.19,13.81 v1(46.24,13.76)
  TOP w0.381: 38.62,20.78 v1(38.62,21) v4(38.62,21.53) ; v1(32.62,21.53) v1(32.62,21) 32.62,20.78 ; 35.62,20.78 v1(35.62,21) v1(35.62,21.53)
  GND2 w0.254: 44.79,16.47 45.12,16.47 45.12,16.22
  SIG3 w0.109: v2(11.31,7.95) 11.35,7.98 15.42,7.98 15.57,7.83 v2(15.6,7.83)
  GND5 w0.127: 7.44,5.95 7.54,5.95
  BOTTOM w0.102: R907.1 v3(24.21,20.96) 24.09,20.96 23.99,20.85 23.99,20.55
  BOTTOM w0.107: C525.2 29.17,9.25 27.18,9.25 26.3,10.13 v3(26.3,10.23)
  BOTTOM w0.203: v3(8.14,15.37) 8.12,15.35 Q801.2
  BOTTOM w0.254: v5(5.62,15.91) v5(5.62,15.27) 5.21,14.86 J801.A12 ; v3(23.67,20.3) 23.67,19.96 23.76,19.86 v3(23.76,19.26) ; v3(7.16,15.65) 7.16,15.98 7.17,16 7.17,16.01 7.21,16.05 v3(7.21,16.45) ; J801.B12 J801.A1 ; J801.A1 5.21,8.14 ; J801.A1 4.34,8.15 4.14,7.95 v5(4.05,7.95) ; J801.B1 J801.A12 ; J801.A12 4.29,14.85 v5(4.14,15) ; C805.2 R804.2 9.43,15.53 v4(9.45,15.55) ; v3(16.9,15.36) 16.67,15.36 v3(16.65,15.35) 16.64,15.36 v3(16.16,15.36) v3(15.91,15.36) ; v3(18.24,13.32) v3(17.99,13.32) v3(17.74,13.32)
  vias: v1(5.78,12.22) v1(6,13.32) v1(7.5,7.21) v1(7.75,7.21) v1(9.3,10.25) v1(9.27,8.47) v1(9.71,11.14) v1(9.71,9.36) v1(9.71,7.58) v1(9.73,6.81) v1(9.8,11.84) v1(10.18,10.25) v1(10.16,8.47) v1(10.6,11.14) v1(10.6,9.36) v1(10.6,7.58) v1(11.07,10.25) v1(11.05,8.47) v1(11.07,4.22) v1(11.38,11.14) v1(11.38,10.89) v1(11.38,10.64) v1(11.38,10.39) v1(11.38,10.14) v1(11.49,9.36) v1(11.63,11.14) v1(11.63,10.89) v1(11.63,10.64) v1(11.63,10.39) v1(11.63,10.14) v1(11.88,11.14) v1(11.88,10.89) v1(11.88,10.64) v1(11.88,10.39) v1(11.88,10.14) v1(12.13,11.14) v1(12.13,10.89) v1(12.13,10.64) v1(12.13,10.39) v1(12.13,10.14) v1(12.27,6.68) v1(12.38,11.14) v1(12.38,10.89) v1(12.38,10.64) v1(12.38,10.39) v1(12.36,9.01) v1(12.91,6.28) v1(13.47,13.05) v1(13.63,9.01) v1(13.6,5.81) v1(13.73,15.89) v1(14.11,16.91) v1(14.11,11.78) v1(14.24,8.98) v1(14.24,8.73) v1(14.38,20.28) v1(14.49,8.98) v1(14.49,8.73) v1(14.45,5.31) v1(14.74,8.98) v1(14.74,8.73) v1(14.73,5.43) v1(14.73,5.18) v1(14.74,15.89) v1(14.74,13.05) v1(14.98,15.04) v1(15,8.26) v1(15,8.01) v1(15,7.76) v1(14.98,5.43) v1(14.98,5.18) v1(15.23,5.43) v1(15.23,5.18) v1(15.25,8.26) v1(15.25,8.01) v1(15.38,16.91) v1(15.38,11.78) v1(15.49,15.04) v1(15.53,8.96) v1(15.53,8.71) v1(15.5,8.26) v1(15.77,15.89) v1(15.78,8.96) v1(15.78,8.71) v1(15.75,8.26) v1(16.01,13.05) v1(16.03,8.96) v1(16.03,8.71) v1(16,8.26) v1(16.65,16.91) v1(16.65,16.05) v1(16.65,11.78) v1(16.75,14.32) v1(17.03,13.71) v1(17.03,13.46) v1(17.08,4.24) v1(17.08,3.99) v1(17.28,13.05) v1(17.33,4.24) v1(17.33,3.99) v1(17.6,15) v1(17.58,4.24) v1(17.58,3.99) v1(17.92,11.78) v1(17.96,19.57) v1(17.96,14.21) v1(18.27,15.02) v1(18.25,14.66) v1(18.25,13.94) v1(18.4,4.16) v1(18.4,3.91) v1(18.4,3.66) v1(18.4,3.41) v1(18.64,16.88) v1(18.55,13.05) v1(18.65,4.16) v1(18.65,3.91) v1(18.65,3.66) v1(18.65,3.41) v1(18.9,4.16) v1(18.9,3.91) v1(18.9,3.66) v1(18.9,3.41) v1(19.19,11.78) v1(19.24,7.39) v1(19.15,4.16) v1(19.15,3.91) v1(19.15,3.66) v1(19.15,3.41) v1(19.29,16.65) v1(19.29,16.4) v1(19.39,11.28) v1(19.39,11.03) v1(19.39,10.78) v1(19.39,10.53) v1(19.39,10.28) v1(19.4,4.16) v1(19.4,3.91) v1(19.4,3.66) v1(19.4,3.41) v1(19.54,16.65) v1(19.54,16.4) v1(19.49,7.39) v1(19.64,11.28) v1(19.64,11.03) v1(19.64,10.78) v1(19.64,10.53) v1(19.64,10.28) v1(19.74,7.39) v1(19.79,16.65) v1(19.79,16.4) v1(19.82,13.05) v1(19.89,11.28) v1(19.89,11.03) v1(19.89,10.78) v1(19.89,10.53) v1(19.89,10.28) v1(19.97,12.53) v1(19.97,12.28) v1(19.97,12.03) v1(19.99,7.39) v1(20.14,11.28) v1(20.14,11.03) v1(20.14,10.78) v1(20.14,10.53) v1(20.14,10.28) v1(20.22,12.53) v1(20.22,12.28) v1(20.22,12.03) v1(20.24,7.39) v1(20.51,16.65) v1(20.51,16.4) v1(20.49,7.39) v1(20.69,13.15) v1(20.74,7.39) v1(20.76,16.65) v1(20.76,16.4) v1(20.78,15.52) v1(21.01,16.65) v1(21.01,16.4) v1(21.03,15.52) v1(21.46,21.53) v1(22.87,21.53) v1(23.33,13.29) v1(23.33,13.04) v1(23.33,12.79) v1(23.33,12.54) v1(23.32,10.32) v1(23.58,13.29) v1(23.58,13.04) v1(23.58,12.79) v1(23.58,12.54) v1(23.79,8.94) v1(23.88,17.02) v1(23.88,15.67) v1(24.04,8.94) v1(24.35,17.68) v1(24.35,17.09) v1(24.37,16.03) v1(24.37,15.78) v1(24.62,15.78) v1(24.94,14.53) v1(24.99,11.61) v1(25.22,10.77) v1(25.22,10.52) v1(25.22,10.27) v1(25.22,10.02) v1(25.49,15.85) v1(25.49,15.6) v1(25.47,10.77) v1(25.47,10.52) v1(25.47,10.27) v1(25.47,10.02) v1(25.74,15.85) v1(25.74,15.6) v1(25.72,10.77) v1(25.72,10.52) v1(25.72,10.27) v1(25.72,10.02) v1(25.99,15.85) v1(25.99,15.6) v1(25.97,10.77) v1(25.97,10.52) v1(25.97,10.27) v1(25.97,10.02) v1(26.2,12.01) v1(26.2,11.76) v1(26.2,11.51) v1(26.2,11.26) v1(26.2,11.01) v1(26.32,14.43) v1(26.32,14.18) v1(26.32,13.93) v1(26.32,13.68) v1(26.32,13.43) v1(26.32,13.18) v1(26.32,12.93) v1(26.53,19.78) v1(26.45,12.01) v1(26.45,11.76) v1(26.45,11.51) v1(26.45,11.26) v1(26.45,11.01) v1(26.57,14.18) v1(26.57,12.93) v1(26.55,12.34) v1(26.7,15.85) v1(26.7,15.6) v1(26.93,12.43) v1(26.95,15.85) v1(26.95,15.6) v1(27.2,15.85) v1(27.2,15.6) v1(27.44,18.78) v1(27.44,17.88) v1(28.18,20.65) v1(28.18,19.51) v1(29.25,21.53) v1(29.43,6.04) v1(29.6,10.73) v1(29.6,10.48) v1(29.6,10.23) v1(29.63,9.35) v1(29.6,5.23) v1(29.77,18.78) v1(29.77,17.85) v1(29.85,10.73) v1(29.85,10.48) v1(29.85,10.23) v1(29.88,9.35) v1(29.96,20.37) v1(30.1,10.73) v1(30.1,10.48) v1(30.1,10.23) v1(30.13,9.35) v1(30.06,5.81) v1(30.06,4.55) v1(30.35,10.73) v1(30.35,10.48) v1(30.35,10.23) v1(30.38,9.35) v1(30.47,16.25) v1(30.6,10.23) v1(30.63,9.35) v1(30.75,3.45) v1(30.84,10.23) v1(30.88,9.35) v1(30.91,1.38) v1(31.09,10.23) v1(31.13,9.35) v1(31.34,10.23) v1(31.38,9.35) v1(31.59,10.23) v1(31.63,9.35) v1(31.84,10.48) v1(31.84,10.23) v1(31.88,9.35) v1(32.09,10.48) v1(32.09,10.23) v1(32.13,9.35) v1(32.34,10.48) v1(32.34,10.23) v1(32.38,9.35) v1(32.62,20.75) v1(32.62,20.5) v1(32.62,20.25) v1(32.62,20) v1(32.59,10.48) v1(32.59,10.23) v1(32.63,9.35) v1(32.84,10.48) v1(32.84,10.23) v1(32.88,9.35) v1(32.93,4.55) v1(33.09,10.48) v1(33.09,10.23) v1(33.13,9.35) v1(33.34,10.48) v1(33.34,10.23) v1(33.38,9.35) v1(33.62,18) v1(33.62,17.75) v1(33.62,17.5) v1(33.62,17.25) v1(33.64,16.25) v1(33.59,10.48) v1(33.59,10.23) v1(33.63,9.35) v1(33.88,9.35) v1(33.99,10.73) v1(33.99,10.48) v1(33.99,10.23) v1(34.13,9.35) v1(34.24,10.73) v1(34.24,10.48) v1(34.24,10.23) v1(34.38,9.35) v1(34.4,1.38) v1(34.49,10.73) v1(34.49,10.48) v1(34.49,10.23) v1(34.74,10.73) v1(34.74,10.48) v1(34.74,10.23) v1(34.92,4.33) v1(34.99,10.73) v1(34.99,10.48) v1(34.99,10.23) v1(35.24,10.73) v1(35.24,10.48) v1(35.24,10.23) v1(35.49,10.73) v1(35.49,10.48) v1(35.49,10.23) v1(35.62,20.75) v1(35.62,20.5) v1(35.62,20.25) v1(35.62,20) v1(35.74,10.73) v1(35.74,10.48) v1(35.74,10.23) v1(36.62,18) v1(36.62,17.75) v1(36.62,17.5) v1(36.62,17.25) v1(36.62,17) v1(36.98,9.99) v1(36.98,9.74) v1(36.98,9.49) v1(36.98,9.24) v1(37.23,9.99) v1(37.23,9.74) v1(37.23,9.49) v1(37.23,9.24) v1(37.35,16.25) v1(37.48,9.99) v1(37.48,9.74) v1(37.48,9.49) v1(37.48,9.24) v1(37.62,18) v1(37.62,17.75) v1(37.62,17.5) v1(37.62,17.25) v1(37.62,17) v1(37.73,9.99) v1(37.73,9.74) v1(37.73,9.49) v1(37.73,9.24) v1(38.62,20.75) v1(38.62,20.5) v1(38.62,20.25) v1(38.62,20) v1(38.62,17.75) v1(38.62,17.5) v1(38.62,17.25) v1(38.62,17) v1(38.67,7.36) v1(39.46,7.36) v1(39.97,8.38) v1(40.32,5.87) v1(40.32,4.49) v1(40.32,3.83) v1(40.47,7.36) v1(40.98,8.38) v1(41.34,4.34) v1(41.34,3.33) v1(41.34,2.31) v1(41.34,1.29) v1(41.49,7.36) v1(42,8.38) v1(42.23,7.62) v1(42.35,3.83) v1(42.52,13.46) v1(42.52,13.21) v1(42.52,12.96) v1(42.52,12.71) v1(42.52,12.46) v1(42.52,12.21) v1(42.52,11.96) v1(42.52,11.71) v1(42.52,11.46) v1(42.52,11.21) v1(42.52,10.96) v1(42.52,10.71) v1(42.52,10.46) v1(42.52,10.21) v1(42.52,9.96) v1(42.54,21.9) v1(42.61,13.96) v1(42.77,13.46) v1(42.77,13.21) v1(42.77,12.96) v1(42.77,12.71) v1(42.77,12.46) v1(42.77,12.21) v1(42.77,11.96) v1(42.77,11.71) v1(42.77,11.46) v1(42.77,11.21) v1(42.77,10.96) v1(42.77,10.71) v1(42.77,10.46) v1(42.77,10.21) v1(42.77,9.96) v1(43.02,13.46) v1(43.02,13.21) v1(43.02,12.96) v1(43.02,12.71) v1(43.02,12.46) v1(43.02,12.21) v1(43.02,11.96) v1(43.02,11.71) v1(43.02,11.46) v1(43.02,11.21) v1(43.02,10.96) v1(43.02,10.71) v1(43.02,10.46) v1(43.02,10.21) v1(43.02,9.96) v1(43.01,9.4) v1(43.01,8.38) v1(43.11,15.96) v1(43.11,15.46) v1(43.11,14.96) v1(43.27,13.46) v1(43.27,13.21) v1(43.37,6.37) v1(43.37,5.36) v1(43.37,4.34) v1(43.34,3.05) v1(43.37,2.31) v1(43.64,11.69) v1(44,10.89) v1(44,10.04) v1(44.51,13.12) v1(44.51,12.87) v1(44.7,14.78) v1(44.76,13.12) v1(44.76,12.87) v1(45.01,13.12) v1(45.12,15.71) v1(45.26,13.12) v1(46,10.53) v1(46.2,14.43) v1(47.22,14.43) v1(47.26,13.76) v1(48,10.53) v1(49,9.1) v1(49,6.56) v1(50,7.99) v2(4.76,11.61) v2(5.13,13.77) v2(5.28,10.7) v2(5.46,5.85) v2(5.97,13.64) v2(5.98,12.9) v2(6.7,7.35) v2(6.81,11.36) v2(7.45,18.21) v2(7.89,12.6) v2(8.13,11.03) v2(8.08,9.45) v2(8.15,11.72) v2(8.69,17.68) v2(9.11,13.97) v2(9.07,9.51) v2(9.07,6.54) v2(9.42,16.93) v2(9.5,12.23) v2(9.81,18.1) v2(9.78,13.31) v2(10.04,8.79) v2(10.06,6.84) v2(10.15,14.87) v2(10.31,13.98) v2(10.36,12.78) v2(10.55,17.36) v2(10.83,15.55) v2(10.97,4.78) v2(11.31,6.04) v2(11.81,16.44) v2(12.58,6.3) v2(12.62,3.81) v2(12.77,11.8) v2(12.77,11.39) v2(12.77,10.99) v2(12.77,10.58) v2(13.17,11.39) v2(13.17,10.99) v2(13.17,10.58) v2(13.17,10.17) v2(13.28,6.02) v2(13.4,15.9) v2(13.58,10.99) v2(13.58,10.58) v2(13.58,10.17) v2(13.6,6.58) v2(13.99,10.58) v2(13.99,10.17) v2(14.42,15.9) v2(14.44,6.58) v2(14.44,6.02) v2(15.28,6.02) v2(15.86,3.81) v2(16.01,7.83) v2(16.41,7.83) v2(16.49,7.42) v2(16.49,7.02) v2(16.61,15.68) v2(16.82,7.83) v2(16.89,7.42) v2(16.89,7.02) v2(17.23,15.34) v2(17.18,14.94) v2(17.22,7.83) v2(17.3,7.42) v2(17.3,7.02) v2(17.36,1.73) v2(17.52,14.68) v2(17.63,7.83) v2(17.74,17.33) v2(17.74,16.93) v2(17.71,7.42) v2(17.71,7.02) v2(17.9,14.54) v2(17.94,14.94) v2(18.04,7.83) v2(18.11,7.42) v2(18.11,7.02) v2(18.15,17.33) v2(18.16,4.48) v2(18.28,14.29) v2(18.44,7.83) v2(18.52,7.42) v2(18.52,7.02) v2(18.55,17.33) v2(18.6,14.95) v2(18.6,14.55) v2(18.96,17.33) v2(19.01,14.95) v2(19.01,14.55) v2(19.27,7.71) v2(19.33,4.72) v2(19.37,17.33) v2(19.42,15.36) v2(19.42,14.95) v2(19.42,14.55) v2(19.57,3.12) v2(19.68,7.71) v2(19.74,4.7) v2(19.82,15.77) v2(19.82,15.36) v2(19.82,14.95) v2(19.82,14.55) v2(19.77,4.29) v2(20.01,20.86) v2(20.03,14.2) v2(20.03,2.61) v2(20.08,7.71) v2(20.23,15.36) v2(20.23,14.95) v2(20.23,14.55) v2(20.17,13.81) v2(20.2,4.8) v2(20.21,4.36) v2(20.49,7.71) v2(20.45,3.6) v2(20.58,4.94) v2(20.58,4.54) v2(20.58,4.13) v2(20.98,4.94) v2(20.98,4.54) v2(20.98,4.13) v2(21.38,18.26) v2(21.39,4.94) v2(21.39,4.54) v2(21.39,4.13) v2(21.8,4.94) v2(21.8,4.54) v2(21.8,4.13) v2(22.01,9.69) v2(22.19,21.53) v2(22.2,4.94) v2(22.2,4.54) v2(22.2,4.13) v2(22.36,18.57) v2(22.42,9.69) v2(22.49,9.28) v2(22.61,4.94) v2(22.61,4.54) v2(22.61,4.13) v2(22.69,8.93) v2(22.83,9.69) v2(22.89,9.28) v2(23.02,4.54) v2(23.02,4.13) v2(23.23,9.69) v2(23.3,9.28) v2(23.42,4.54) v2(23.42,4.13) v2(23.64,9.69) v2(23.71,9.28) v2(23.83,4.13) v2(24.04,9.69) v2(24.11,9.28) v2(24.45,9.69) v2(24.52,9.28) v2(24.52,8.88) v2(24.52,8.47) v2(24.65,21.53) v2(24.68,13.66) v2(24.86,9.69) v2(24.92,9.28) v2(24.92,8.88) v2(24.92,8.47) v2(24.95,13.97) v2(25.23,13.66) v2(25.26,9.69) v2(25.33,9.28) v2(25.33,8.88) v2(25.33,8.47) v2(25.62,14.22) v2(25.69,13.66) v2(25.67,9.69) v2(25.74,9.28) v2(25.74,8.88) v2(25.74,8.47) v2(25.92,14.53) v2(26,14.04) v2(26.08,9.69) v2(26.14,9.28) v2(26.14,8.88) v2(26.14,8.47) v2(26.31,14.76) v2(26.48,9.69) v2(26.51,4.32) v2(26.51,3.91) v2(26.55,9.28) v2(26.55,8.88) v2(26.55,8.47) v2(26.83,16.44) v2(26.89,9.69) v2(26.92,4.32) v2(26.92,3.91) v2(26.96,9.28) v2(26.96,8.88) v2(26.96,8.47) v2(27.11,19.17) v2(27.11,17.88) v2(27.24,16.44) v2(27.64,16.44) v2(27.71,14.69) v2(27.9,14.33) v2(27.92,4.32) v2(27.92,3.91) v2(27.96,13.93) v2(28.05,16.44) v2(28.12,14.69) v2(28.32,14.33) v2(28.33,4.32) v2(28.33,3.91) v2(28.35,8.23) v2(28.35,7.69) v2(28.35,6.95) v2(28.52,19.22) v2(28.46,16.44) v2(28.53,14.69) v2(28.73,4.32) v2(28.73,3.91) v2(28.86,16.44) v2(29.27,16.44) v2(29.33,8.26) v2(29.33,7.86) v2(29.33,7.45) v2(29.68,16.44) v2(29.73,8.26) v2(29.73,7.86) v2(29.73,7.45) v2(29.91,19.19) v2(29.88,18.41) v2(30.14,8.26) v2(30.14,7.86) v2(30.14,7.45) v2(30.42,21.53) v2(30.42,4.34) v2(30.54,8.26) v2(30.54,7.86) v2(30.54,7.45) v2(30.7,10.96) v2(30.7,10.56) v2(30.95,8.26) v2(30.95,7.86) v2(30.95,7.45) v2(31.1,11.37) v2(31.1,10.96) v2(31.1,10.56) v2(31.34,3.28) v2(31.51,10.96) v2(31.51,10.56) v2(31.46,1.53) v2(31.67,18.41) v2(31.94,10.84) v2(32.09,13.03) v2(32.35,10.84) v2(32.7,4.04) v2(32.75,10.84) v2(33.11,13.03) v2(33.16,10.84) v2(33.32,16.33) v2(33.25,1.53) v2(33.57,10.84) v2(33.67,1.98) v2(34.06,17.85) v2(34.12,13.03) v2(34.51,2.94) v2(35.13,13.03) v2(35.55,2.74) v2(36.14,13.66) v2(36.63,11.6) v2(36.63,11.19) v2(36.63,10.78) v2(36.63,10.38) v2(36.62,9.97) v2(36.61,9.56) v2(36.67,16.15) v2(36.71,8.73) v2(36.96,17.81) v2(36.95,17.24) v2(36.96,16.44) v2(37.04,11.6) v2(37.04,11.19) v2(37.04,10.78) v2(37.04,10.38) v2(37.05,15.03) v2(37.12,8.73) v2(37.12,8.32) v2(37.24,18.1) v2(37.24,17.52) v2(37.25,16.73) v2(37.43,1.98) v2(37.53,18.38) v2(37.45,11.6) v2(37.45,11.19) v2(37.45,10.78) v2(37.45,10.38) v2(37.53,8.73) v2(37.53,8.32) v2(37.53,7.92) v2(37.85,11.6) v2(37.85,11.19) v2(37.85,10.78) v2(37.85,10.38) v2(37.93,8.73) v2(37.93,8.32) v2(37.93,7.92) v2(38.29,20.78) v2(38.28,16.28) v2(38.26,11.6) v2(38.26,11.19) v2(38.26,10.78) v2(38.26,10.38) v2(38.26,9.97) v2(38.34,8.73) v2(38.34,8.32) v2(38.34,7.92) v2(38.58,16.54) v2(38.75,8.73) v2(38.75,8.32) v2(38.75,7.92) v2(38.89,16.81) v2(39.1,19.53) v2(39.2,17.07) v2(39.15,8.73) v2(39.15,8.32) v2(39.15,7.92) v2(39.41,15.85) v2(39.41,2.74) v2(39.69,10.11) v2(39.81,3.86) v2(40.96,4.6) v2(41.59,17.02) v2(41.78,20.9) v2(41.78,18.98) v2(42.01,4.98) v2(42.89,5.36) v2(43.28,7.29) v2(43.36,12.83) v2(43.36,12.43) v2(43.45,14.15) v2(43.76,12.83) v2(43.76,12.43) v2(43.76,12.02) v2(43.8,5.1) v2(44.77,9.98) v2(44.77,8.66) v2(44.77,7.29) v2(44.77,5.81) v2(45,4.43) v2(45.73,13.82) v2(46,12.49) v2(46.09,16.38) v2(46.16,7.29) v2(46.34,4.43) v2(46.79,11.08) v2(46.79,8.54) v2(46.79,5.77) v2(47.61,13.76) v2(47.61,12.49) v2(47.56,7.29) v2(48.17,9.29) v2(48.17,6.83) v2(49.03,13.31) v3(5.08,19.41) v3(5.99,14.74) v3(6.32,15.17) v3(6.48,13.64) v3(6.58,14.14) v3(6.59,12.27) v3(6.96,12.28) v3(7.04,11.01) v3(6.98,9.42) v3(7.42,13.55) v3(7.44,12.27) v3(7.44,10.98) v3(7.59,9.51) v3(7.75,19.03) v3(8,12.99) v3(8.14,15.12) v3(8.25,13.65) v3(8.46,9.61) v3(9.37,10.52) v3(9.47,12.66) v3(9.51,11.89) v3(10.03,5.13) v3(10.07,17.78) v3(10.35,14.43) v3(10.54,5.13) v3(10.55,16.15) v3(13.83,16.87) v3(14.08,16.87) v3(14.11,5.43) v3(14.11,5.18) v3(14.33,16.87) v3(14.33,16.62) v3(14.35,10.57) v3(14.35,10.32) v3(14.35,10.07) v3(14.35,9.82) v3(14.58,16.87) v3(14.58,16.62) v3(14.6,10.82) v3(14.6,10.57) v3(14.6,10.32) v3(14.6,10.07) v3(14.6,9.82) v3(14.6,9.57) v3(14.6,9.32) v3(14.6,9.07) v3(14.6,8.82) v3(14.83,16.87) v3(14.83,16.62) v3(14.85,10.82) v3(14.85,10.57) v3(14.85,10.32) v3(14.85,10.07) v3(14.85,9.82) v3(14.85,9.57) v3(14.85,9.32) v3(14.85,9.07) v3(14.85,8.82) v3(14.85,8.57) v3(15.08,16.94) v3(15.08,16.69) v3(15.1,10.82) v3(15.1,10.57) v3(15.1,10.32) v3(15.1,10.07) v3(15.1,9.82) v3(15.1,9.57) v3(15.1,9.32) v3(15.1,9.07) v3(15.1,8.82) v3(15.1,8.57) v3(15.1,8.32) v3(15.34,16.94) v3(15.35,9.82) v3(15.35,9.57) v3(15.35,9.32) v3(15.35,9.07) v3(15.35,8.82) v3(15.35,8.57) v3(15.35,8.32) v3(15.46,10.04) v3(15.6,9.82) v3(15.6,9.57) v3(15.6,9.32) v3(15.6,9.07) v3(15.6,8.82) v3(15.6,8.57) v3(15.6,8.32) v3(15.85,9.57) v3(15.85,9.32) v3(15.85,9.07) v3(15.85,8.82) v3(15.85,8.57) v3(15.85,8.32) v3(16.1,9.57) v3(16.1,9.32) v3(16.1,9.07) v3(16.1,8.82) v3(16.1,8.57) v3(16.1,8.32) v3(16.35,9.57) v3(16.35,9.32) v3(16.35,9.07) v3(16.35,8.82) v3(16.37,8.56) v3(16.48,10.54) v3(16.48,10.29) v3(16.48,10.04) v3(16.48,9.79) v3(16.6,9.57) v3(16.6,9.32) v3(16.6,9.07) v3(16.73,10.54) v3(16.73,10.29) v3(16.73,10.04) v3(16.73,9.79) v3(16.85,9.57) v3(16.85,9.32) v3(16.98,9.79) v3(17.1,9.57) v3(17.14,10.05) v3(17.23,9.79) v3(17.69,16.36) v3(17.74,13.82) v3(17.74,13.57) v3(17.99,14.07) v3(17.99,13.82) v3(17.99,13.57) v3(18.24,13.82) v3(18.24,13.57) v3(18.49,13.99) v3(18.49,13.74) v3(18.49,13.49) v3(18.6,14.22) v3(18.74,13.99) v3(18.74,13.74) v3(18.74,13.49) v3(18.9,14.22) v3(18.99,13.99) v3(18.99,13.74) v3(18.99,13.49) v3(19.21,6.28) v3(19.21,6.03) v3(19.21,5.78) v3(19.21,5.53) v3(19.21,5.28) v3(19.21,5.03) v3(19.24,14.24) v3(19.24,13.99) v3(19.24,13.74) v3(19.24,13.49) v3(19.53,14.24) v3(19.49,13.99) v3(19.49,13.74) v3(19.49,13.49) v3(19.46,6.28) v3(19.46,6.03) v3(19.46,5.78) v3(19.46,5.53) v3(19.46,5.28) v3(19.46,5.03) v3(19.71,6.28) v3(19.71,6.03) v3(19.71,5.78) v3(19.71,5.53) v3(19.71,5.28) v3(19.71,5.03) v3(19.75,13.88) v3(19.75,13.63) v3(19.75,13.38) v3(19.96,6.28) v3(19.96,6.03) v3(19.96,5.78) v3(19.96,5.53) v3(19.96,5.28) v3(19.96,5.03) v3(20.09,13.49) v3(20.05,3.89) v3(20.21,6.28) v3(20.21,6.03) v3(20.21,5.78) v3(20.33,5.44) v3(20.33,5.19) v3(20.3,3.89) v3(20.36,13.49) v3(20.62,6.23) v3(20.69,13.15) v3(21.07,15.5) v3(21.62,16.05) v3(21.63,11.68) v3(22.34,13.17) v3(22.43,16.24) v3(22.59,15.56) v3(22.6,11.93) v3(22.6,11.68) v3(22.6,11.43) v3(22.6,11.18) v3(22.6,10.93) v3(22.6,10.68) v3(22.6,10.43) v3(22.85,11.93) v3(22.85,11.68) v3(22.85,11.43) v3(22.85,11.18) v3(22.85,10.93) v3(22.85,10.68) v3(22.85,10.43) v3(23.1,11.93) v3(23.1,11.68) v3(23.1,11.43) v3(23.1,11.18) v3(23.1,10.93) v3(23.1,10.68) v3(23.37,15.04) v3(23.35,11.93) v3(23.35,11.68) v3(23.35,11.43) v3(23.35,11.18) v3(23.35,10.93) v3(23.35,10.68) v3(23.61,14.96) v3(23.6,11.93) v3(23.6,11.68) v3(23.6,11.43) v3(23.6,11.18) v3(23.6,10.93) v3(23.6,10.68) v3(23.65,15.23) v3(23.84,15.44) v3(23.93,12.99) v3(23.85,11.93) v3(23.85,11.68) v3(23.85,11.43) v3(23.85,11.18) v3(23.85,10.93) v3(23.85,10.68) v3(24.1,11.18) v3(24.1,10.93) v3(24.1,10.68) v3(24.18,3.88) v3(24.43,3.88) v3(24.46,20.96) v3(24.48,15.43) v3(24.61,15.67) v3(24.57,13) v3(24.57,2.69) v3(24.68,3.88) v3(24.86,15.67) v3(24.88,12.6) v3(24.93,3.88) v3(25.09,4.76) v3(25.24,15.65) v3(25.24,15.4) v3(25.18,3.88) v3(25.43,3.88) v3(25.49,15.82) v3(25.49,15.57) v3(25.49,15.32) v3(25.49,15.07) v3(25.5,5.68) v3(25.63,4.76) v3(25.74,15.57) v3(25.74,15.32) v3(25.74,15.07) v3(25.7,4.28) v3(25.68,3.88) v3(25.78,20.44) v3(25.77,12.6) v3(25.77,11.48) v3(25.77,10.36) v3(25.84,5.59) v3(25.93,4.38) v3(25.93,4.13) v3(25.93,3.88) v3(25.99,15.57) v3(25.99,15.32) v3(25.99,15.07) v3(25.95,4.88) v3(25.95,4.63) v3(26.24,15.57) v3(26.24,15.32) v3(26.24,15.07) v3(26.19,5.4) v3(26.19,5.15) v3(26.19,4.9) v3(26.19,4.65) v3(26.18,4.38) v3(26.18,4.13) v3(26.18,3.88) v3(26.3,11) v3(26.49,15.57) v3(26.49,15.32) v3(26.49,15.07) v3(26.44,5.4) v3(26.44,5.15) v3(26.44,4.9) v3(26.44,4.65) v3(26.63,12.98) v3(26.74,15.57) v3(26.74,15.32) v3(26.74,15.07) v3(26.69,5.4) v3(26.69,5.15) v3(26.69,4.9) v3(26.69,4.65) v3(26.79,11.95) v3(26.99,15.57) v3(26.99,15.32) v3(26.99,15.07) v3(26.94,5.4) v3(26.94,5.15) v3(26.94,4.9) v3(26.94,4.65) v3(27.06,14.04) v3(27.24,15.57) v3(27.24,15.32) v3(27.24,15.07) v3(27.19,5.4) v3(27.19,5.15) v3(27.19,4.9) v3(27.19,4.65) v3(27.34,2.33) v3(27.49,15.57) v3(27.49,15.32) v3(27.49,15.07) v3(27.49,14.35) v3(27.49,13.66) v3(27.44,5.4) v3(27.44,5.15) v3(27.44,4.9) v3(27.44,4.65) v3(27.69,5.4) v3(27.69,5.15) v3(27.69,4.9) v3(27.69,4.65) v3(28.45,11.33) v3(28.7,14.25) v3(28.7,13.74) v3(28.7,13.23) v3(28.7,12.73) v3(28.83,2.33) v3(28.89,12.11) v3(28.89,11.25) v3(29.02,10.74) v3(29.22,14.25) v3(29.22,13.41) v3(29.28,10.37) v3(29.28,10.12) v3(29.28,9.37) v3(29.42,9.87) v3(29.42,9.62) v3(29.41,8.88) v3(29.41,8.63) v3(29.53,10.37) v3(29.53,10.12) v3(29.53,9.37) v3(29.65,13.74) v3(29.67,9.87) v3(29.67,9.62) v3(29.66,8.88) v3(29.66,8.63) v3(29.78,10.37) v3(29.78,10.12) v3(29.92,9.87) v3(29.92,9.62) v3(29.91,8.88) v3(29.91,8.63) v3(30.03,10.37) v3(30.03,10.12) v3(30.09,14.48) v3(30.17,9.87) v3(30.17,9.62) v3(30.16,8.88) v3(30.16,8.63) v3(30.21,3.15) v3(30.28,10.37) v3(30.28,10.12) v3(30.31,2.33) v3(30.42,9.87) v3(30.42,9.62) v3(30.41,8.88) v3(30.41,8.63) v3(30.53,10.12) v3(30.66,8.88) v3(30.66,8.63) v3(30.91,8.88) v3(30.91,8.63) v3(31.17,9.87) v3(31.17,9.62) v3(31.16,8.88) v3(31.16,8.63) v3(31.42,9.87) v3(31.42,9.62) v3(31.41,8.88) v3(31.41,8.63) v3(31.63,19.45) v3(31.67,9.87) v3(31.67,9.62) v3(31.67,9.22) v3(31.67,8.97) v3(31.8,2.33) v3(31.92,9.87) v3(31.92,9.62) v3(31.92,9.22) v3(31.92,8.97) v3(31.97,18.24) v3(32.17,9.87) v3(32.17,9.62) v3(32.17,9.22) v3(32.17,8.97) v3(32.42,9.22) v3(32.42,8.97) v3(32.67,9.22) v3(32.67,8.97) v3(32.93,19.45) v3(32.93,10.37) v3(32.93,10.12) v3(32.93,9.87) v3(32.93,9.62) v3(32.92,9.22) v3(32.92,8.97) v3(33.11,18.24) v3(33.18,10.37) v3(33.18,10.12) v3(33.18,9.87) v3(33.18,9.62) v3(33.17,9.22) v3(33.17,8.97) v3(33.43,10.37) v3(33.43,10.12) v3(33.43,9.87) v3(33.43,9.62) v3(33.42,9.22) v3(33.42,8.97) v3(33.68,10.37) v3(33.68,10.12) v3(33.68,9.87) v3(33.68,9.62) v3(33.67,9.22) v3(33.67,8.97) v3(33.77,20.56) v3(33.77,20.31) v3(33.82,3.96) v3(33.93,10.37) v3(33.93,10.12) v3(33.93,9.87) v3(33.93,9.62) v3(33.92,9.22) v3(33.92,8.97) v3(34.15,15.95) v3(34.17,9.22) v3(34.17,8.97) v3(34.42,9.22) v3(34.42,8.97) v3(34.67,10.37) v3(34.67,10.12) v3(34.67,9.87) v3(34.67,9.62) v3(34.67,9.22) v3(34.67,8.97) v3(34.66,4.11) v3(34.92,10.37) v3(34.92,10.12) v3(34.92,9.87) v3(34.92,9.62) v3(34.92,9.22) v3(34.92,8.97) v3(35.17,10.37) v3(35.17,10.12) v3(35.17,9.87) v3(35.17,9.62) v3(35.17,9.22) v3(35.17,8.97) v3(35.17,8.72) v3(36.57,9.21) v3(36.87,4.98) v3(36.92,3.75) v3(37,9.07) v3(37.05,9.82) v3(37.05,9.57) v3(37.05,9.32) v3(37.3,9.82) v3(37.3,9.57) v3(37.3,9.32) v3(37.25,9.07) v3(37.46,2.88) v3(37.63,16.8) v3(37.55,9.82) v3(37.55,9.57) v3(37.55,9.32) v3(37.55,9.07) v3(37.81,16.98) v3(37.81,16.62) v3(37.8,9.57) v3(37.8,9.32) v3(37.76,3.53) v3(37.99,17.16) v3(37.99,16.8) v3(37.99,16.45) v3(38.19,20.29) v3(38.17,17.33) v3(38.17,16.98) v3(38.17,16.62) v3(38.35,17.15) v3(38.35,16.8) v3(38.39,5.08) v3(38.53,16.98) v3(39.08,4.65) v3(39.06,3.28) v3(39.79,16.99) v3(39.81,4.67) v3(39.86,2.23) v3(40.42,18.13) v3(40.73,16.15) v3(41.64,15.19) v3(42.49,16.03) v3(48.68,12.72) v3(48.68,10.18) v3(48.68,7.64) v4(4.27,12.79) v4(4.27,10.61) v4(6.15,12.37) v4(6.15,10.65) v4(6.72,10.65) v4(8.46,13.09) v4(8.46,12.48) v4(8.61,10.83) v4(11.21,18.11) v4(11.62,18.51) v4(12.03,18.92) v4(21.1,3.27) v4(21.73,3.27) v4(22.37,3.27) v4(23,3.27) v4(23.64,3.27) v4(24.27,3.27) v4(25.4,21.53) v4(25.91,21.53) v4(26.42,21.53) v4(26.62,1.53) v4(26.92,21.53) v4(27.43,21.53) v4(27.94,21.53) v4(28.03,3.27) v4(28.45,21.53) v4(28.66,3.27) v4(29.3,3.27) v4(29.72,21.53) v4(29.67,1.53) v4(30.99,21.53) v4(32.26,21.53) v4(33.26,3.7) v4(33.53,21.53) v4(33.64,4.42) v4(34.8,21.53) v4(34.99,3.7) v4(35.42,19.3) v4(35.61,3.43) v4(36.07,21.53) v4(36.08,4.01) v4(36.83,18.93) v4(36.83,18.43) v4(37.34,21.53) v4(37.34,18.93) v4(38.28,9.49) v4(38.81,9.49) v4(38.8,1.46) v4(39.35,9.49) v4(39.88,9.49) v4(40.41,9.49) v4(40.95,9.49) v4(43.36,18.16) v4(43.36,17.63) v4(43.96,17.43) v4(44.5,17.43) v4(46.1,17.43) v4(46.63,17.43) v4(47.16,17.43) v4(47.7,17.43) v4(48.23,17.43) v5(0.53,15.21) v5(0.53,12.8) v5(0.53,10.38) v5(0.53,7.97) v5(2.23,15.56) v5(2.23,14.92) v5(2.15,7.95) v5(2.15,7.32) v5(2.39,1.74) v5(2.78,7.95) v5(2.78,7.32) v5(2.92,21.67) v5(2.87,15.56) v5(2.87,14.92) v5(3.42,7.95) v5(3.42,7.32) v5(3.5,15.63) v5(3.5,15) v5(5.1,18.8) v5(5.12,4.56) v5(5.12,3.92) v5(5.54,22.49) v5(5.54,0.52) v5(5.75,4.56) v5(5.75,3.92) v5(6.39,4.56) v5(6.39,3.92) v5(6.6,19.36) v5(8.58,22.49) v5(8.55,19.36) v5(8.58,0.52) v5(9.2,3.72) v5(9.2,3.08) v5(9.83,3.72) v5(9.83,3.08) v5(9.83,2.45) v5(10.49,21.31) v5(10.49,19.36) v5(10.47,3.72) v5(10.47,3.08) v5(10.47,2.45) v5(10.47,1.81) v5(11.1,3.72) v5(11.1,3.08) v5(11.1,2.45) v5(11.1,1.81) v5(11.63,22.49) v5(11.63,0.52) v5(11.74,3.72) v5(11.74,3.08) v5(11.74,2.45) v5(11.74,1.81) v5(12.43,21.31) v5(13.76,17.43) v5(14.38,21.31) v5(14.39,17.43) v5(14.68,22.49) v5(15.03,17.43) v5(15.66,17.43) v5(16.3,17.43) v5(16.73,3.04) v5(16.73,2.43) v5(16.93,17.43) v5(17.39,3.04) v5(17.39,2.43) v5(17.73,22.49) v5(17.73,0.52) v5(18.05,3.04) v5(18.05,2.43) v5(18.26,21.31) v5(19.6,22.49) v5(20.52,1.53) v5(20.78,20.99) v5(23.57,1.53) v5(23.79,21.49) v5(24.85,3.32) v5(25.49,3.32) v5(26.12,3.32) v5(26.76,3.32) v5(32.09,4.14) v5(35.21,1.53) v5(36.02,1.53) v5(40.37,2.89) v5(40.65,22.49) v5(40.66,0.52) v5(41.79,1.9) v5(42.2,2.89) v5(43.42,22.49) v5(43.46,0.52) v5(44.6,3.55) v5(45.55,2.08) v5(46.1,20.38) v5(46.25,0.52) v5(46.84,22.49) v5(49.02,17.5) v5(49.02,16.86) v5(49.12,4.82) v5(49.12,4.19) v5(49.05,0.52) v5(49.66,17.5) v5(49.66,16.86) v5(49.76,4.82) v5(49.76,4.19) v5(50.67,15.6) v5(50.67,12.81) v5(50.67,10.02) v5(50.67,7.22) v5(51.49,4.68) v5(51.84,0.52) v5(52.31,17.01) v5(52.42,22.49) v5(52.63,2.9) v5(54.2,5.98) v5(54.66,0.72) v5(55.1,17.01) v5(56.11,21.29) v5(56.59,2.34) v5(57.02,17.69) v5(57,5.98)
